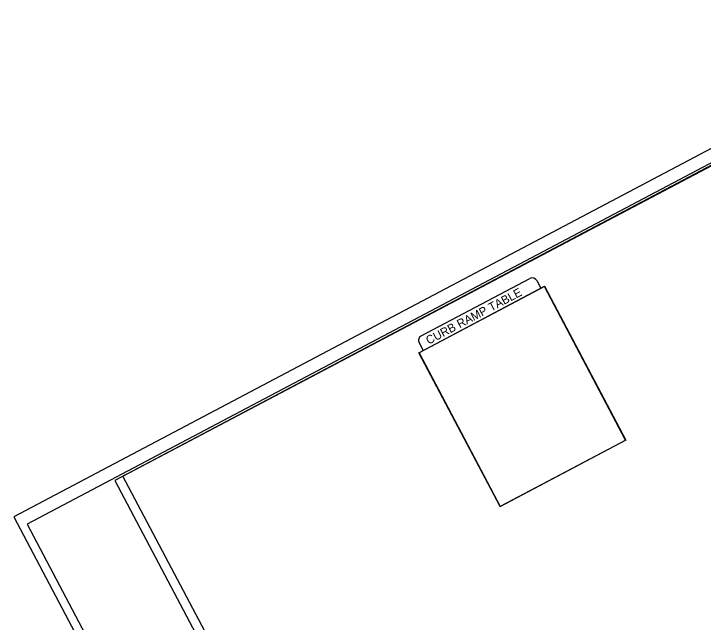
# Model space of a CAD drawing. Extents: x 1487176 to 1489663, y 497841 to 500965.
# Drawn here: x 1487342 to 1488420, y 498792 to 499742 of the extents above; entities that cross this region are included whole.
import ezdxf

# ---------------------------------------------------------------- set-up
doc = ezdxf.new("R2010")
doc.units = 0
for name, color, linetype in [('Default', 7, 'Continuous'), ('DEV TUBULAR MARKER PLAN VIEW CELL', 7, 'Continuous'), ('MARK STRAIGHT ARROW CELL', 7, 'Continuous'), ('Prop Mkg Solid Dbl Yel Rpm 80ft', 7, 'Continuous'), ('Prop Mkg Solid White Lane Line', 7, 'Continuous'), ('Scratch_Level_1', 7, 'Continuous'), ('Scratch_Level_6', 7, 'Continuous')]:
    doc.layers.add(name, color=color, linetype=linetype)

msp = doc.modelspace()

# ---------------------------------------------------------------- linework, layer by layer
at = {"layer": 'DEV TUBULAR MARKER PLAN VIEW CELL'}
msp.add_lwpolyline([(1488120.4, 498369.2), (1487949.5, 498194.2), (1487512.6, 499019.7), (1488662.1, 499625.8), (1488771.3, 499418.8), (1488936.6, 499506), (1489317.2, 498785.2), (1488242.7, 498217.8)], close=True, dxfattribs=at)
at = {"layer": 'MARK STRAIGHT ARROW CELL'}
msp.add_lwpolyline([(1488830.6, 499742), (1487342.4, 498956.2), (1487854.1, 497987.1), (1489342.3, 498772.9)], close=True, dxfattribs=at)
at = {"layer": 'Prop Mkg Solid Dbl Yel Rpm 80ft'}
for points in [[(1487975.2, 499212.6), (1488171.8, 499316.4), (1488298.8, 499076), (1488102.1, 498972.2)], [(1488102.3, 498972.6), (1488298.4, 499076.1), (1488171.7, 499316.1), (1487975.6, 499212.5)]]:
    msp.add_lwpolyline(points, close=True, dxfattribs=at)
at = {"layer": 'Prop Mkg Solid White Lane Line'}
msp.add_lwpolyline([(1488826.9, 499713.7), (1487500.5, 499013.3), (1487990.8, 498084.8), (1489317.2, 498785.2)], close=True, dxfattribs=at)
at = {"layer": 'Scratch_Level_1'}
msp.add_lwpolyline([(1488835.9, 499722.2), (1487363.2, 498944.6), (1487856.2, 498010.8), (1489329, 498788.5)], close=True, dxfattribs=at)
at = {"layer": 'Scratch_Level_6'}
for p, q in [((1487979, 499238.9), (1488148.8, 499328.5)), ((1488159.7, 499325.2), (1488165.9, 499313.3)), ((1487975.7, 499228.1), (1487981.9, 499216.2))]:
    msp.add_line(p, q, dxfattribs=at)
for centre, start, end in [((1488152.6, 499321.5), 27.8351, 117.8351), ((1487982.7, 499231.8), 117.8351, 207.8351)]:
    msp.add_arc(centre, 8, start, end, dxfattribs=at)

# ---------------------------------------------------------------- texts
at = {"layer": 'Default'}
msp.add_text('CURB RAMP TABLE', height=13.173, rotation=27.8652, dxfattribs=at).set_placement((1487990.6, 499225))

doc.saveas('drawing.dxf')
